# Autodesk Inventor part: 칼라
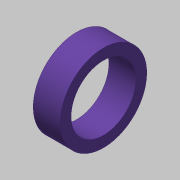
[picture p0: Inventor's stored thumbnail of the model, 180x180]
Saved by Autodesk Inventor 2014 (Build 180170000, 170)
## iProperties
Created: 2020-04
Part Number: 칼라
Material: 강철, 연강
Document SubType Name: Modeling
Designer: mduedu
Density: 1 g/cm^3
Appearance: 보라색
Author: mduedu
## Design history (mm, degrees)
sketch "스케치1"
  geometry: C1 r 8 at (0, 0); C2 r 6 at (0, 0); 1 further point
  constraints: 2 centre point, 2 coincident
  dimensions: "d0" = 16 diameter of C1; "d1" = 12 diameter of C2
extrude "돌출1" new body sketch "스케치1" distance "d2" = 5; taper "d3" = 0 deg
node "솔리드1"
